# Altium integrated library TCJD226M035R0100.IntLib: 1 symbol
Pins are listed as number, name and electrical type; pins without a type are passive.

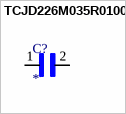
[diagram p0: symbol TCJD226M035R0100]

## TCJD226M035R0100
designator C?
Capacitor: tantalum-polymer; 22uF; 35VDC; Case: D; 2917; ESR:100mÎ©; MP: TCJD226M035R0100
footprint CAPPM7343X310N
pins: 1, 2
